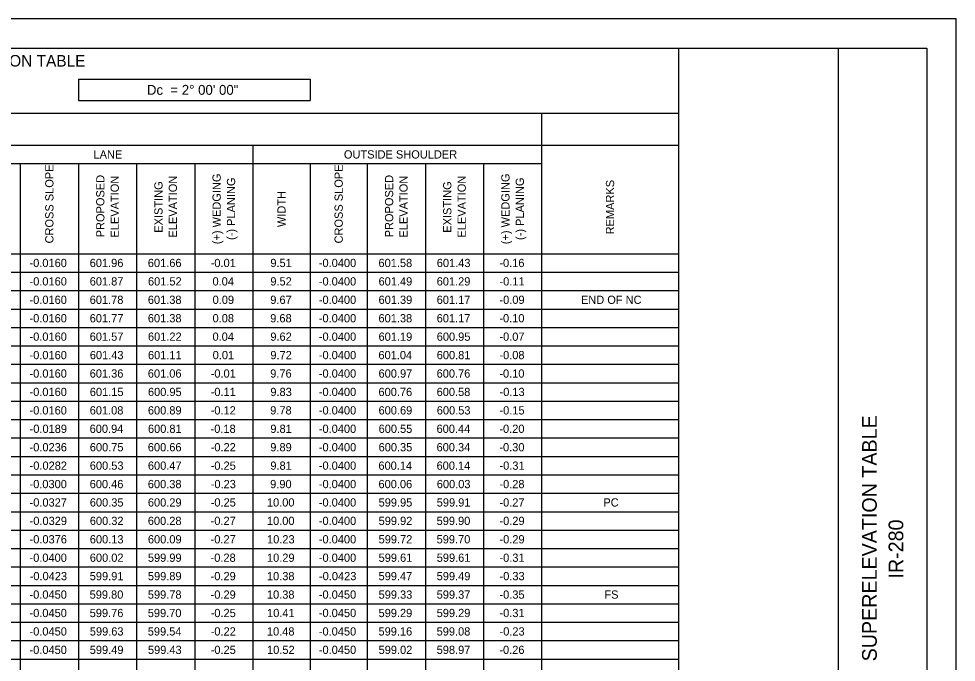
# Model space of a CAD drawing. Extents: x 0 to 34, y 0 to 22.
# Drawn here: x 18.07 to 34, y 11.07 to 22 of the extents above; entities that cross this region are included whole.
import ezdxf

# ---------------------------------------------------------------- set-up
doc = ezdxf.new("R2010")
doc.units = 0
for name, color, linetype in [('SH_Border', 7, 'Continuous'), ('SH_Cut_Line', 7, 'Continuous'), ('SH_Data', 7, 'Continuous'), ('SH_Text', 7, 'Continuous')]:
    doc.layers.add(name, color=color, linetype=linetype)

msp = doc.modelspace()

# ---------------------------------------------------------------- linework, layer by layer
at = {"layer": 'SH_Border'}
msp.add_line((32, 0.5), (32, 21.5), dxfattribs=at)
msp.add_lwpolyline([(1.5, 21.5), (33.5, 21.5), (33.5, 0.5), (1.5, 0.5)], close=True, dxfattribs=at)
at = {"layer": 'SH_Cut_Line'}
msp.add_lwpolyline([(0, 0), (34, 0), (34, 22), (0, 22)], close=True, dxfattribs=at)
at = {"layer": 'SH_Text'}
for p, q in [((4.225, 21.5), (29.277, 21.5)), ((29.277, 21.5), (29.277, 0.484)), ((19.081, 20.973), (23.018, 20.973)), ((19.081, 20.973), (19.081, 20.611)), ((23.018, 20.973), (23.018, 20.611)), ((19.081, 20.611), (23.018, 20.611)), ((4.225, 20.396), (29.277, 20.396)), ((26.954, 20.396), (26.954, 0.484)), ((4.225, 19.853), (29.277, 19.853)), ((22.046, 19.853), (22.046, 0.484)), ((6.317, 19.54), (26.954, 19.54)), ((18.093, 19.54), (18.093, 0.484)), ((19.081, 19.54), (19.081, 0.484)), ((20.07, 19.54), (20.07, 0.484)), ((21.058, 19.54), (21.058, 0.484)), ((23.018, 19.54), (23.018, 0.484)), ((23.99, 19.54), (23.99, 0.484)), ((24.978, 19.54), (24.978, 0.484)), ((25.966, 19.54), (25.966, 0.484)), ((4.225, 18.008), (29.277, 18.008)), ((4.225, 17.695), (29.277, 17.695)), ((4.225, 17.382), (29.277, 17.382)), ((4.225, 17.069), (29.277, 17.069)), ((4.225, 16.756), (29.277, 16.756)), ((4.225, 16.444), (29.277, 16.444)), ((4.225, 16.131), (29.277, 16.131)), ((4.225, 15.818), (29.277, 15.818)), ((4.225, 15.505), (29.277, 15.505)), ((4.225, 15.192), (29.277, 15.192)), ((4.225, 14.879), (29.277, 14.879)), ((4.225, 14.566), (29.277, 14.566)), ((4.225, 14.253), (29.277, 14.253)), ((4.225, 13.94), (29.277, 13.94)), ((4.225, 13.627), (29.277, 13.627)), ((4.225, 13.314), (29.277, 13.314)), ((4.225, 13.001), (29.277, 13.001)), ((4.225, 12.688), (29.277, 12.688)), ((4.225, 12.375), (29.277, 12.375)), ((4.225, 12.062), (29.277, 12.062)), ((4.225, 11.749), (29.277, 11.749)), ((4.225, 11.436), (29.277, 11.436)), ((4.225, 11.124), (29.277, 11.124))]:
    msp.add_line(p, q, dxfattribs=at)

# ---------------------------------------------------------------- texts
at = {"layer": 'SH_Data'}
for s, p in [('SUPERELEVATION TABLE', (32.65, 11.084)), ('IR-280', (33.1, 12.491))]:
    msp.add_text(s, height=0.25, rotation=90, dxfattribs=at).set_placement(p)
at = {"layer": 'SH_Text'}
for s, height, p in [('WOO/LUC-280-06.20/00.00 - SUPERELEVATION TABLE', 0.196, (12.442, 21.188)), ('Dc  = 2° 00\' 00"', 0.168, (20.245, 20.708)), ('LANE', 0.14, (19.338, 19.626)), ('OUTSIDE SHOULDER', 0.14, (23.593, 19.626)), ('-0.0160', 0.14, (18.25, 17.782)), ('601.96', 0.14, (19.273, 17.782)), ('601.66', 0.14, (20.261, 17.782)), ('-0.01', 0.14, (21.329, 17.782)), ('9.51', 0.14, (22.343, 17.782)), ('-0.0400', 0.14, (23.167, 17.782)), ('601.58', 0.14, (24.181, 17.782)), ('601.43', 0.14, (25.172, 17.782)), ('-0.16', 0.14, (26.235, 17.782)), ('-0.0160', 0.14, (18.25, 17.469)), ('601.87', 0.14, (19.273, 17.469)), ('601.52', 0.14, (20.263, 17.469)), ('0.04', 0.14, (21.36, 17.469)), ('9.52', 0.14, (22.343, 17.469)), ('-0.0400', 0.14, (23.167, 17.469)), ('601.49', 0.14, (24.182, 17.469)), ('601.29', 0.14, (25.17, 17.469)), ('-0.11', 0.14, (26.237, 17.469)), ('-0.0160', 0.14, (18.25, 17.156)), ('601.78', 0.14, (19.273, 17.156)), ('601.38', 0.14, (20.261, 17.156)), ('0.09', 0.14, (21.362, 17.156)), ('9.67', 0.14, (22.342, 17.156)), ('-0.0400', 0.14, (23.167, 17.156)), ('601.39', 0.14, (24.182, 17.156)), ('601.17', 0.14, (25.17, 17.156)), ('-0.09', 0.14, (26.237, 17.156)), ('END OF NC', 0.14, (27.622, 17.156)), ('-0.0160', 0.14, (18.25, 16.843)), ('601.77', 0.14, (19.273, 16.843)), ('601.38', 0.14, (20.261, 16.843)), ('0.08', 0.14, (21.361, 16.843)), ('9.68', 0.14, (22.341, 16.843)), ('-0.0400', 0.14, (23.167, 16.843)), ('601.38', 0.14, (24.181, 16.843)), ('601.17', 0.14, (25.17, 16.843)), ('-0.10', 0.14, (26.235, 16.843)), ('-0.0160', 0.14, (18.25, 16.53)), ('601.57', 0.14, (19.273, 16.53)), ('601.22', 0.14, (20.263, 16.53)), ('0.04', 0.14, (21.36, 16.53)), ('9.62', 0.14, (22.343, 16.53)), ('-0.0400', 0.14, (23.167, 16.53)), ('601.19', 0.14, (24.182, 16.53)), ('600.95', 0.14, (25.171, 16.53)), ('-0.07', 0.14, (26.236, 16.53)), ('-0.0160', 0.14, (18.25, 16.217)), ('601.43', 0.14, (19.275, 16.217)), ('601.11', 0.14, (20.263, 16.217)), ('0.01', 0.14, (21.363, 16.217)), ('9.72', 0.14, (22.343, 16.217)), ('-0.0400', 0.14, (23.167, 16.217)), ('601.04', 0.14, (24.18, 16.217)), ('600.81', 0.14, (25.171, 16.217)), ('-0.08', 0.14, (26.236, 16.217)), ('-0.0160', 0.14, (18.25, 15.904)), ('601.36', 0.14, (19.273, 15.904)), ('601.06', 0.14, (20.261, 15.904)), ('-0.01', 0.14, (21.329, 15.904)), ('9.76', 0.14, (22.341, 15.904)), ('-0.0400', 0.14, (23.167, 15.904)), ('600.97', 0.14, (24.182, 15.904)), ('600.76', 0.14, (25.169, 15.904)), ('-0.10', 0.14, (26.235, 15.904)), ('-0.0160', 0.14, (18.25, 15.591)), ('601.15', 0.14, (19.275, 15.591)), ('600.95', 0.14, (20.263, 15.591)), ('-0.11', 0.14, (21.329, 15.591)), ('9.83', 0.14, (22.343, 15.591)), ('-0.0400', 0.14, (23.167, 15.591)), ('600.76', 0.14, (24.181, 15.591)), ('600.58', 0.14, (25.169, 15.591)), ('-0.13', 0.14, (26.238, 15.591)), ('-0.0160', 0.14, (18.25, 15.278)), ('601.08', 0.14, (19.273, 15.278)), ('600.89', 0.14, (20.262, 15.278)), ('-0.12', 0.14, (21.329, 15.278)), ('9.78', 0.14, (22.341, 15.278)), ('-0.0400', 0.14, (23.167, 15.278)), ('600.69', 0.14, (24.182, 15.278)), ('600.53', 0.14, (25.172, 15.278)), ('-0.15', 0.14, (26.237, 15.278)), ('-0.0189', 0.14, (18.252, 14.965)), ('600.94', 0.14, (19.272, 14.965)), ('600.81', 0.14, (20.263, 14.965)), ('-0.18', 0.14, (21.327, 14.965)), ('9.81', 0.14, (22.343, 14.965)), ('-0.0400', 0.14, (23.167, 14.965)), ('600.55', 0.14, (24.183, 14.965)), ('600.44', 0.14, (25.168, 14.965)), ('-0.20', 0.14, (26.235, 14.965)), ('-0.0236', 0.14, (18.251, 14.652)), ('600.75', 0.14, (19.275, 14.652)), ('600.66', 0.14, (20.261, 14.652)), ('-0.22', 0.14, (21.329, 14.652)), ('9.89', 0.14, (22.342, 14.652)), ('-0.0400', 0.14, (23.167, 14.652)), ('600.35', 0.14, (24.183, 14.652)), ('600.34', 0.14, (25.168, 14.652)), ('-0.30', 0.14, (26.235, 14.652)), ('-0.0282', 0.14, (18.252, 14.339)), ('600.53', 0.14, (19.275, 14.339)), ('600.47', 0.14, (20.262, 14.339)), ('-0.25', 0.14, (21.329, 14.339)), ('9.81', 0.14, (22.343, 14.339)), ('-0.0400', 0.14, (23.167, 14.339)), ('600.14', 0.14, (24.18, 14.339)), ('600.14', 0.14, (25.168, 14.339)), ('-0.31', 0.14, (26.237, 14.339)), ('-0.0300', 0.14, (18.25, 14.026)), ('600.46', 0.14, (19.273, 14.026)), ('600.38', 0.14, (20.261, 14.026)), ('-0.23', 0.14, (21.33, 14.026)), ('9.90', 0.14, (22.34, 14.026)), ('-0.0400', 0.14, (23.167, 14.026)), ('600.06', 0.14, (24.181, 14.026)), ('600.03', 0.14, (25.172, 14.026)), ('-0.28', 0.14, (26.236, 14.026)), ('-0.0327', 0.14, (18.251, 13.714)), ('600.35', 0.14, (19.275, 13.714)), ('600.29', 0.14, (20.262, 13.714)), ('-0.25', 0.14, (21.329, 13.714)), ('10.00', 0.14, (22.285, 13.714)), ('-0.0400', 0.14, (23.167, 13.714)), ('599.95', 0.14, (24.183, 13.714)), ('599.91', 0.14, (25.171, 13.714)), ('-0.27', 0.14, (26.236, 13.714)), ('PC', 0.14, (28.003, 13.714)), ('-0.0329', 0.14, (18.252, 13.401)), ('600.32', 0.14, (19.275, 13.401)), ('600.28', 0.14, (20.261, 13.401)), ('-0.27', 0.14, (21.328, 13.401)), ('10.00', 0.14, (22.285, 13.401)), ('-0.0400', 0.14, (23.167, 13.401)), ('599.92', 0.14, (24.183, 13.401)), ('599.90', 0.14, (25.169, 13.401)), ('-0.29', 0.14, (26.237, 13.401)), ('-0.0376', 0.14, (18.251, 13.088)), ('600.13', 0.14, (19.275, 13.088)), ('600.09', 0.14, (20.262, 13.088)), ('-0.27', 0.14, (21.328, 13.088)), ('10.23', 0.14, (22.287, 13.088)), ('-0.0400', 0.14, (23.167, 13.088)), ('599.72', 0.14, (24.183, 13.088)), ('599.70', 0.14, (25.169, 13.088)), ('-0.29', 0.14, (26.237, 13.088)), ('-0.0400', 0.14, (18.25, 12.775)), ('600.02', 0.14, (19.275, 12.775)), ('599.99', 0.14, (20.262, 12.775)), ('-0.28', 0.14, (21.327, 12.775)), ('10.29', 0.14, (22.286, 12.775)), ('-0.0400', 0.14, (23.167, 12.775)), ('599.61', 0.14, (24.183, 12.775)), ('599.61', 0.14, (25.171, 12.775)), ('-0.31', 0.14, (26.237, 12.775)), ('-0.0423', 0.14, (18.253, 12.462)), ('599.91', 0.14, (19.274, 12.462)), ('599.89', 0.14, (20.262, 12.462)), ('-0.29', 0.14, (21.328, 12.462)), ('10.38', 0.14, (22.285, 12.462)), ('-0.0423', 0.14, (23.17, 12.462)), ('599.47', 0.14, (24.182, 12.462)), ('599.49', 0.14, (25.17, 12.462)), ('-0.33', 0.14, (26.238, 12.462)), ('-0.0450', 0.14, (18.25, 12.149)), ('599.80', 0.14, (19.272, 12.149)), ('599.78', 0.14, (20.261, 12.149)), ('-0.29', 0.14, (21.328, 12.149)), ('10.38', 0.14, (22.285, 12.149)), ('-0.0450', 0.14, (23.167, 12.149)), ('599.33', 0.14, (24.183, 12.149)), ('599.37', 0.14, (25.17, 12.149)), ('-0.35', 0.14, (26.237, 12.149)), ('FS', 0.14, (28.02, 12.149)), ('-0.0450', 0.14, (18.25, 11.836)), ('599.76', 0.14, (19.273, 11.836)), ('599.70', 0.14, (20.26, 11.836)), ('-0.25', 0.14, (21.329, 11.836)), ('10.41', 0.14, (22.287, 11.836)), ('-0.0450', 0.14, (23.167, 11.836)), ('599.29', 0.14, (24.182, 11.836)), ('599.29', 0.14, (25.17, 11.836)), ('-0.31', 0.14, (26.237, 11.836)), ('-0.0450', 0.14, (18.25, 11.523)), ('599.63', 0.14, (19.275, 11.523)), ('599.54', 0.14, (20.26, 11.523)), ('-0.22', 0.14, (21.329, 11.523)), ('10.48', 0.14, (22.285, 11.523)), ('-0.0450', 0.14, (23.167, 11.523)), ('599.16', 0.14, (24.181, 11.523)), ('599.08', 0.14, (25.169, 11.523)), ('-0.23', 0.14, (26.238, 11.523)), ('-0.0450', 0.14, (18.25, 11.21)), ('599.49', 0.14, (19.274, 11.21)), ('599.43', 0.14, (20.263, 11.21)), ('-0.25', 0.14, (21.329, 11.21)), ('10.52', 0.14, (22.287, 11.21)), ('-0.0450', 0.14, (23.167, 11.21)), ('599.02', 0.14, (24.183, 11.21)), ('598.97', 0.14, (25.17, 11.21)), ('-0.26', 0.14, (26.235, 11.21))]:
    msp.add_text(s, height=height, dxfattribs=at).set_placement(p)
for s, p in [('CROSS SLOPE', (18.657, 18.183)), ('CROSS SLOPE', (23.574, 18.183)), ('PROPOSED ', (19.523, 18.287)), ('ELEVATION', (19.768, 18.283)), ('ELEVATION', (20.756, 18.283)), ('(+) WEDGING', (21.5, 18.17)), ('(-) PLANING', (21.745, 18.242)), ('PROPOSED ', (24.431, 18.287)), ('ELEVATION', (24.676, 18.283)), ('ELEVATION', (25.665, 18.283)), ('(+) WEDGING', (26.408, 18.17)), ('(-) PLANING', (26.653, 18.242)), ('EXISTING ', (20.511, 18.365)), ('EXISTING ', (25.42, 18.365)), ('REMARKS', (28.186, 18.337)), ('WIDTH', (22.602, 18.461))]:
    msp.add_text(s, height=0.14, rotation=90, dxfattribs=at).set_placement(p)

doc.saveas('drawing.dxf')
